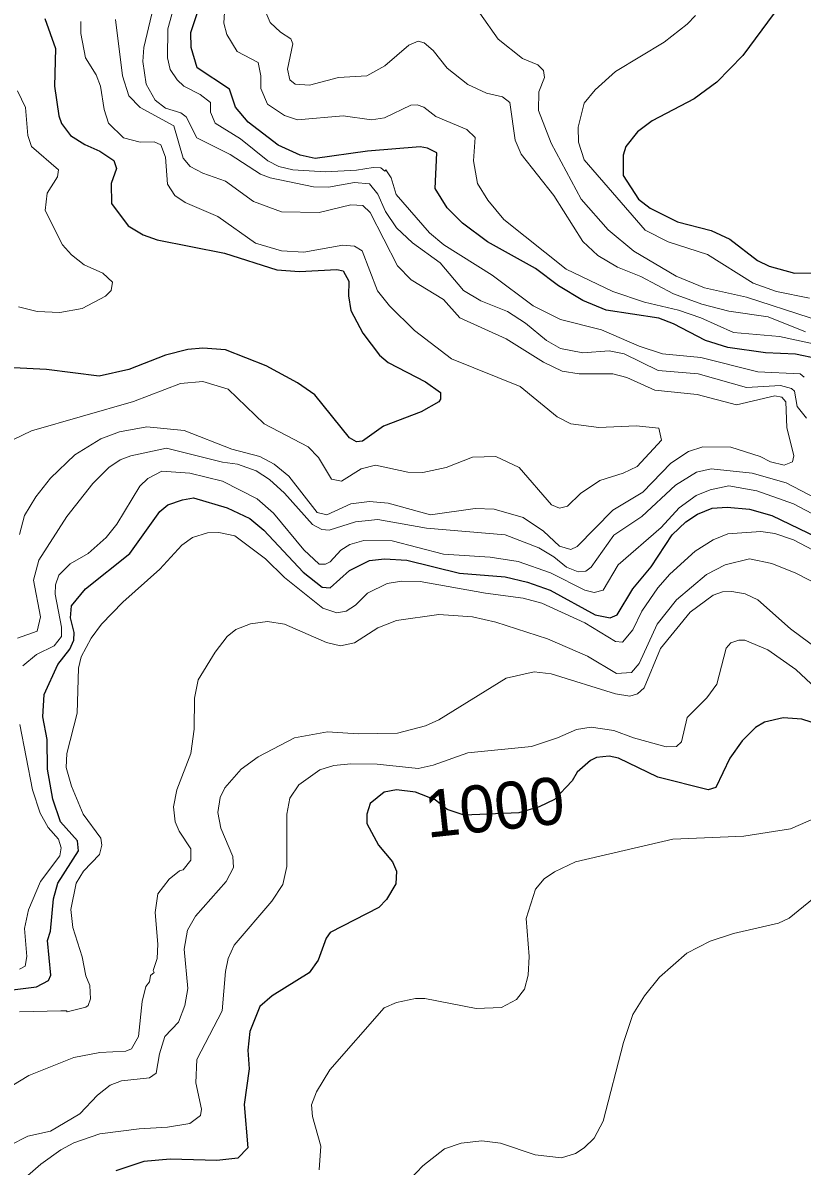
# Model space of a CAD drawing. Extents: x 265 to 291.4, y 7731.5 to 7759.6.
# Drawn here: x 275.919 to 277.244, y 7748.785 to 7750.728 of the extents above; entities that cross this region are included whole.
import ezdxf
from ezdxf.enums import TextEntityAlignment as Align

# ---------------------------------------------------------------- set-up
doc = ezdxf.new("R2010")
doc.units = 0
doc.header["$LTSCALE"] = 0.032
for name, color, linetype, lineweight in [('1', 7, 'Continuous', 25), ('2', 7, 'Continuous', 13), ('61', 7, 'Continuous', 13)]:
    doc.layers.add(name, color=color, linetype=linetype, lineweight=lineweight)

msp = doc.modelspace()

# ---------------------------------------------------------------- linework, layer by layer
at = {"layer": '1'}
for points in [[(277.2702, 7750.1568), (277.2321, 7750.1648), (277.1812, 7750.1671), (277.1175, 7750.1759), (277.0793, 7750.1878), (277.0252, 7750.2165), (276.9998, 7750.226), (276.9107, 7750.2395), (276.8709, 7750.2562), (276.8295, 7750.2809), (276.7906, 7750.3103), (276.7086, 7750.3557), (276.6665, 7750.3875), (276.6402, 7750.4138), (276.6195, 7750.4464), (276.6227, 7750.5068), (276.6068, 7750.5148), (276.5941, 7750.5171), (276.505, 7750.51), (276.4159, 7750.4973), (276.3904, 7750.5028), (276.353, 7750.5203), (276.3021, 7750.5593), (276.2806, 7750.5848), (276.2703, 7750.615), (276.2154, 7750.6516), (276.2051, 7750.6858), (276.2043, 7750.7113), (276.2337, 7750.8004)], [(277.2169, 7750.7733), (277.1429, 7750.6723), (277.0984, 7750.6269), (277.0602, 7750.5991), (276.9886, 7750.5617), (276.964, 7750.5426), (276.9441, 7750.518), (276.9393, 7750.5029), (276.9393, 7750.4686), (276.9655, 7750.4281), (276.9854, 7750.4129), (277.0316, 7750.3899), (277.0889, 7750.3748), (277.1207, 7750.3604), (277.1676, 7750.3238), (277.1875, 7750.3143), (277.2305, 7750.3024), (277.2734, 7750.3032)], [(275.9561, 7750.7351), (275.9744, 7750.6842), (275.9728, 7750.6206), (275.9799, 7750.5697), (275.9847, 7750.557), (275.9998, 7750.5363), (276.0245, 7750.5211), (276.05, 7750.51), (276.0738, 7750.4941), (276.0778, 7750.4806), (276.069, 7750.4551), (276.0698, 7750.4209), (276.0977, 7750.3827), (276.1232, 7750.3676), (276.147, 7750.3589), (276.2616, 7750.3366), (276.3507, 7750.3079), (276.3889, 7750.3056), (276.4525, 7750.3087)], [(276.4525, 7750.3087), (276.4636, 7750.3063), (276.4731, 7750.2889), (276.4724, 7750.2642), (276.4763, 7750.2388), (276.497, 7750.2006), (276.5249, 7750.1632)], [(276.5249, 7750.1632), (276.54, 7750.1504), (276.6036, 7750.1178), (276.6291, 7750.0995), (276.6291, 7750.0884), (276.6259, 7750.0836), (276.5957, 7750.0669), (276.532, 7750.0422), (276.4962, 7750.0168), (276.4859, 7750.016), (276.474, 7750.0224), (276.4151, 7750.0956), (276.3857, 7750.1162), (276.3324, 7750.1449), (276.2632, 7750.1719), (276.225, 7750.1751), (276.1995, 7750.1727), (276.1613, 7750.1632), (276.0993, 7750.1385), (276.0484, 7750.1274), (275.9593, 7750.1385), (275.8352, 7750.1449)], [(275.8781, 7749.0813), (275.9418, 7749.0893), (275.9625, 7749.1004), (275.9664, 7749.1092), (275.9609, 7749.168), (275.9656, 7749.1839), (275.9708, 7749.2388), (275.9781, 7749.2659), (276.0134, 7749.3208), (276.0118, 7749.3375), (275.9831, 7749.3701), (275.9696, 7749.4083), (275.9609, 7749.4592), (275.9601, 7749.5101), (275.9529, 7749.5483), (275.9553, 7749.5865), (275.9784, 7749.6374), (275.999, 7749.6636), (276.0054, 7749.6787), (276.0062, 7749.6915), (275.9998, 7749.7169), (276.0014, 7749.7368), (276.0253, 7749.7662), (276.1009, 7749.8259), (276.1518, 7749.8975), (276.1653, 7749.9086), (276.19, 7749.9174), (276.2091, 7749.9205), (276.2663, 7749.9038), (276.3045, 7749.8855), (276.3284, 7749.8657), (276.3952, 7749.7941), (276.4278, 7749.7686), (276.4413, 7749.7678), (276.474, 7749.7972), (276.5082, 7749.8139), (276.5336, 7749.8171), (276.5718, 7749.8147), (276.6609, 7749.7925), (276.7389, 7749.7861), (276.777, 7749.7774), (276.8152, 7749.7638)], [(277.0228, 7749.8577), (277.0459, 7749.88), (277.0658, 7749.8927), (277.0905, 7749.903), (277.1159, 7749.9046), (277.1541, 7749.9015), (277.1923, 7749.8903), (277.2687, 7749.8537)], [(276.8152, 7749.7638), (276.8916, 7749.7217), (276.9171, 7749.7169), (276.929, 7749.7217), (276.956, 7749.7662), (276.987, 7749.8036), (277.0228, 7749.8577)], [(277.2591, 7749.5395), (277.2432, 7749.5443), (277.2114, 7749.5467), (277.1796, 7749.5395), (277.1644, 7749.53), (277.1414, 7749.5077), (277.1207, 7749.4783), (277.0968, 7749.4281), (277.0841, 7749.4241), (276.9982, 7749.4456), (276.9314, 7749.4782), (276.9155, 7749.4814), (276.894, 7749.479), (276.8836, 7749.4743), (276.8614, 7749.4544), (276.8526, 7749.4393), (276.8226, 7749.4077), (276.7967, 7749.3951), (276.7621, 7749.3851), (276.6692, 7749.3811), (276.64, 7749.3911), (276.62, 7749.407), (276.5861, 7749.4202), (276.5543, 7749.4241), (276.5328, 7749.4202), (276.509, 7749.4011), (276.5034, 7749.3828), (276.5034, 7749.3669), (276.5232, 7749.3303), (276.5471, 7749.3017), (276.5543, 7749.2858), (276.5527, 7749.2643), (276.5368, 7749.238), (276.5241, 7749.2245), (276.4414, 7749.1815), (276.4342, 7749.172), (276.4206, 7749.1346), (276.4055, 7749.1131), (276.3427, 7749.0741), (276.322, 7749.0558), (276.3045, 7749.0137), (276.3013, 7748.9819), (276.3037, 7748.9501), (276.295, 7748.8896), (276.3013, 7748.8156), (276.2846, 7748.7981), (276.2488, 7748.7941), (276.1693, 7748.7965), (276.1247, 7748.7925), (276.077, 7748.7766)]]:
    msp.add_lwpolyline(points, dxfattribs=at)
at = {"layer": '2'}
for points in [[(276.3459, 7750.8982), (276.3435, 7750.8672), (276.3276, 7750.8099), (276.3268, 7750.7574), (276.3395, 7750.7288), (276.357, 7750.7121), (276.3745, 7750.7009)], [(276.1828, 7750.7813), (276.1653, 7750.7176), (276.1645, 7750.6683), (276.1693, 7750.6484), (276.1812, 7750.6309), (276.1924, 7750.6206), (276.2202, 7750.6063), (276.2377, 7750.5927), (276.2377, 7750.576), (276.2456, 7750.5577), (276.2886, 7750.5307), (276.3355, 7750.4933), (276.3538, 7750.4838), (276.3777, 7750.4782), (276.4334, 7750.475), (276.4859, 7750.4774), (276.5145, 7750.4822), (276.5273, 7750.4814), (276.5344, 7750.4758), (276.536, 7750.4782), (276.5447, 7750.4647), (276.5535, 7750.436), (276.61, 7750.3708), (276.6347, 7750.3509), (276.7166, 7750.2992), (276.7866, 7750.2467), (276.8327, 7750.2236), (276.9027, 7750.2061), (276.9664, 7750.1783), (277.0061, 7750.1656), (277.0714, 7750.1592), (277.1684, 7750.1345), (277.24, 7750.1314), (277.2472, 7750.1258)], [(276.6004, 7750.5848), (276.5893, 7750.5888), (276.5782, 7750.588), (276.5336, 7750.5665), (276.5114, 7750.5633), (276.4636, 7750.5697), (276.3857, 7750.5633), (276.3634, 7750.5705), (276.3347, 7750.5896), (276.3236, 7750.6166), (276.3236, 7750.6381), (276.3188, 7750.6604), (276.283, 7750.6794), (276.2655, 7750.7081), (276.2608, 7750.7272), (276.2632, 7750.7749)], [(277.4349, 7750.1043), (277.411, 7750.117), (277.3649, 7750.1528), (277.3546, 7750.1672), (277.353, 7750.2029), (277.3442, 7750.2149), (277.3227, 7750.2204), (277.2575, 7750.2268), (277.1493, 7750.2618), (277.0777, 7750.2777), (277.0292, 7750.2976), (276.9576, 7750.3398), (276.9139, 7750.3764), (276.8677, 7750.4281), (276.8168, 7750.5235), (276.7953, 7750.5792), (276.7961, 7750.611), (276.8057, 7750.6349), (276.8041, 7750.6468), (276.7945, 7750.6564), (276.7683, 7750.6675), (276.7269, 7750.7001), (276.6959, 7750.7447)], [(276.9632, 7749.9738), (277.0045, 7750.0184), (276.9998, 7750.0391), (276.9616, 7750.0431), (276.898, 7750.0399), (276.8502, 7750.0462), (276.8272, 7750.0582), (276.7643, 7750.1099), (276.6474, 7750.1568), (276.5845, 7750.2053), (276.5424, 7750.2467), (276.5217, 7750.2722), (276.4954, 7750.3406), (276.4825, 7750.3486), (276.4626, 7750.3499), (276.3968, 7750.3382), (276.3586, 7750.3406), (276.3141, 7750.3533), (276.2504, 7750.3986), (276.1948, 7750.4225), (276.1773, 7750.4344), (276.1645, 7750.4535), (276.1613, 7750.4997), (276.1534, 7750.5204), (276.1423, 7750.5259), (276.1184, 7750.5251), (276.0897, 7750.5323), (276.0643, 7750.5577), (276.0571, 7750.5808), (276.0508, 7750.6206), (276.0436, 7750.6397), (276.0253, 7750.6683), (276.0173, 7750.7097), (276.0173, 7750.7304)], [(276.0762, 7750.7336), (276.0881, 7750.6381), (276.0993, 7750.6039), (276.1184, 7750.584), (276.1757, 7750.553), (276.1916, 7750.4981), (276.2035, 7750.4838), (276.225, 7750.4726), (276.2632, 7750.4591), (276.3109, 7750.4241), (276.3586, 7750.4066), (276.4223, 7750.4058), (276.4764, 7750.4185), (276.497, 7750.4177), (276.509, 7750.4058), (276.5559, 7750.3151), (276.5789, 7750.2913), (276.6339, 7750.2578), (276.6617, 7750.2268), (276.7405, 7750.191)], [(277.2511, 7750.0558), (277.2352, 7750.0757), (277.2305, 7750.1019), (277.2257, 7750.1067), (277.2066, 7750.1115), (277.1493, 7750.1083), (277.0666, 7750.1314), (276.999, 7750.1369), (276.9409, 7750.1656), (276.9155, 7750.1703), (276.8709, 7750.1671), (276.8327, 7750.1743), (276.8088, 7750.1878), (276.7731, 7750.2173), (276.7428, 7750.2372), (276.6975, 7750.2555), (276.6681, 7750.273), (276.6283, 7750.3199), (276.5814, 7750.3541), (276.5543, 7750.3796), (276.5352, 7750.4074), (276.5225, 7750.4368), (276.5082, 7750.4543), (276.4827, 7750.4567), (276.4382, 7750.4488), (276.4127, 7750.4495), (276.3395, 7750.4647), (276.3228, 7750.471), (276.2711, 7750.5044), (276.2146, 7750.5323), (276.1963, 7750.5681), (276.1876, 7750.5752), (276.1613, 7750.5832), (276.1438, 7750.5967), (276.1287, 7750.6238), (276.1231, 7750.662), (276.1247, 7750.6858), (276.1383, 7750.7431)], [(277.0626, 7750.7407), (277.0483, 7750.7256), (277.0093, 7750.6954), (276.9266, 7750.6452), (276.8916, 7750.6142), (276.8733, 7750.5912), (276.863, 7750.5506), (276.8637, 7750.5251), (276.8733, 7750.4949), (276.9767, 7750.3756), (277.0157, 7750.3557), (277.0825, 7750.3342), (277.1605, 7750.2857), (277.2002, 7750.2714), (277.2559, 7750.2602)], [(276.3745, 7750.7009), (276.3777, 7750.6922), (276.3689, 7750.6492), (276.3729, 7750.6309), (276.3817, 7750.6238), (276.4063, 7750.6222), (276.4557, 7750.6349), (276.5034, 7750.6381), (276.5344, 7750.6548), (276.575, 7750.6898), (276.5909, 7750.6969), (276.6012, 7750.6938), (276.6163, 7750.681), (276.6402, 7750.6508), (276.6752, 7750.623), (276.707, 7750.6086), (276.7341, 7750.6023), (276.7468, 7750.5927), (276.7556, 7750.5283), (276.7659, 7750.5045), (276.8216, 7750.4344), (276.8709, 7750.3565), (276.8964, 7750.3326), (276.9298, 7750.3127), (276.9696, 7750.2968), (277.0252, 7750.2674), (277.073, 7750.2499), (277.1191, 7750.238), (277.1859, 7750.2284), (277.2496, 7750.2029)], [(275.9116, 7750.2451), (275.9434, 7750.2372), (275.9816, 7750.2356), (276.0197, 7750.2427), (276.0595, 7750.2634), (276.0691, 7750.273), (276.0714, 7750.2873), (276.0547, 7750.3024), (276.0229, 7750.3167), (276.0014, 7750.3334), (275.9863, 7750.3509), (275.9569, 7750.409), (275.9601, 7750.4384), (275.9776, 7750.4663), (275.9792, 7750.4782), (275.9338, 7750.518), (275.9275, 7750.5363), (275.9235, 7750.584), (275.91, 7750.6126)], [(276.7094, 7750.4265), (276.6919, 7750.4551), (276.6848, 7750.4933), (276.6879, 7750.5331), (276.6736, 7750.5466), (276.6211, 7750.5689), (276.6004, 7750.5848)], [(277.2917, 7750.1759), (277.205, 7750.195), (277.1271, 7750.2014), (277.0714, 7750.2268), (277.0332, 7750.2395), (276.9759, 7750.2531), (276.9218, 7750.2714), (276.8423, 7750.3095), (276.7365, 7750.3939), (276.7094, 7750.4265)], [(276.7405, 7750.191), (276.8041, 7750.1512), (276.8359, 7750.1361), (276.8646, 7750.1314), (276.9218, 7750.1314), (276.9457, 7750.125), (276.9934, 7750.1035)], [(275.9028, 7750.02), (275.9338, 7750.0343), (276.1072, 7750.0844), (276.1868, 7750.1147), (276.225, 7750.1186), (276.2679, 7750.1051), (276.3292, 7750.0462), (276.404, 7750.0073), (276.4215, 7749.989), (276.4437, 7749.9524), (276.4604, 7749.9492), (276.4938, 7749.9699), (276.5185, 7749.9762), (276.5734, 7749.9643), (276.5989, 7749.9635), (276.6386, 7749.9723), (276.6832, 7749.9898), (276.723, 7749.9906), (276.7627, 7749.9723), (276.8176, 7749.9086)], [(276.9934, 7750.1035), (277.065, 7750.0964), (277.1318, 7750.0789), (277.1971, 7750.094), (277.209, 7750.0916), (277.2161, 7750.0836), (277.2177, 7750.0399), (277.2297, 7749.9922), (277.2273, 7749.9818), (277.213, 7749.9762), (277.1899, 7749.9818), (277.1724, 7749.9906), (277.1223, 7750.0065), (277.0746, 7750.0073), (277.0507, 7749.9993), (277.0205, 7749.9794), (276.9727, 7749.9301), (276.9218, 7749.8999), (276.8614, 7749.8378), (276.8502, 7749.833), (276.8311, 7749.8386), (276.8041, 7749.8641), (276.7691, 7749.8871), (276.7198, 7749.9015), (276.688, 7749.9023), (276.6116, 7749.8919), (276.54, 7749.9118), (276.5082, 7749.9142), (276.4764, 7749.9102), (276.4358, 7749.8919), (276.4191, 7749.8959), (276.3713, 7749.9572), (276.3459, 7749.9778), (276.322, 7749.9906), (276.2743, 7750.0033), (276.1932, 7750.0351), (276.1295, 7750.0415), (276.0834, 7750.0327), (276.0516, 7750.0208), (276.007, 7749.9937), (275.9657, 7749.954), (275.941, 7749.9222), (275.9219, 7749.8903), (275.9131, 7749.8585)], [(275.91, 7749.6819), (275.9434, 7749.6938), (275.9489, 7749.7185), (275.937, 7749.7806), (275.9458, 7749.8148), (275.9935, 7749.8887), (276.038, 7749.9452), (276.0651, 7749.9723), (276.0842, 7749.985), (276.1025, 7749.9922), (276.1629, 7750.0049), (276.2584, 7749.981), (276.2838, 7749.9778), (276.3157, 7749.9667), (276.3379, 7749.9516), (276.3634, 7749.9285), (276.4111, 7749.8752), (276.427, 7749.8665), (276.4398, 7749.8657), (276.4843, 7749.88), (276.5225, 7749.884), (276.6052, 7749.8688), (276.7389, 7749.8577), (276.7961, 7749.8354), (276.8216, 7749.8203), (276.8431, 7749.8028), (276.863, 7749.7949), (276.8757, 7749.7957), (276.8852, 7749.8028), (276.9234, 7749.8569), (276.9711, 7749.8887), (277.0284, 7749.942), (277.0642, 7749.9643), (277.0889, 7749.9699), (277.1589, 7749.9627), (277.2162, 7749.946), (277.3052, 7749.8999)], [(276.8176, 7749.9086), (276.8311, 7749.903), (276.8446, 7749.9062), (276.8669, 7749.9277), (276.8996, 7749.95), (276.9393, 7749.9627), (276.9632, 7749.9738)], [(276.2027, 7749.9627), (276.155, 7749.9659), (276.1311, 7749.9532), (276.1176, 7749.9404), (276.0786, 7749.876), (276.0603, 7749.8529), (276.0301, 7749.8259)], [(277.314, 7749.8657), (277.2289, 7749.9102), (277.1668, 7749.9325), (277.1191, 7749.9412), (277.0873, 7749.9341), (277.0634, 7749.9245), (277.0348, 7749.9038), (277.0037, 7749.8704), (276.9306, 7749.8068), (276.9051, 7749.7638), (276.89, 7749.7599), (276.8741, 7749.7638), (276.816, 7749.7933), (276.7611, 7749.8124), (276.7134, 7749.8195), (276.6339, 7749.8251), (276.5464, 7749.8474), (276.4986, 7749.8482), (276.4748, 7749.841), (276.4596, 7749.8315), (276.4413, 7749.8116), (276.4334, 7749.8076), (276.4223, 7749.8076), (276.3968, 7749.8323), (276.3451, 7749.8943), (276.3172, 7749.919), (276.2584, 7749.9492), (276.2027, 7749.9627)], [(276.0094, 7749.2659), (276.022, 7749.2858), (276.0492, 7749.3144), (276.0531, 7749.3303), (276.0515, 7749.3422), (276.0213, 7749.3828), (276.0014, 7749.4305), (275.9927, 7749.4624), (275.9935, 7749.4862), (276.011, 7749.5546), (276.0134, 7749.631), (276.0181, 7749.6501), (276.0348, 7749.6819), (276.0523, 7749.7058), (276.0889, 7749.7432), (276.1518, 7749.7996), (276.1892, 7749.8402), (276.2075, 7749.8529), (276.2329, 7749.8609), (276.252, 7749.8617), (276.2791, 7749.8561), (276.3316, 7749.8171), (276.3634, 7749.7853), (276.4286, 7749.7328), (276.4525, 7749.7249), (276.4684, 7749.728), (276.4843, 7749.7384), (276.505, 7749.7583), (276.5384, 7749.775), (276.5623, 7749.779), (276.5941, 7749.7782), (276.7055, 7749.7583), (276.7691, 7749.7503), (276.8009, 7749.7416), (276.8741, 7749.7082), (276.9266, 7749.6763), (276.9385, 7749.6755), (276.956, 7749.6962), (276.9711, 7749.7281), (276.9982, 7749.7678), (277.0189, 7749.7909), (277.0618, 7749.8299), (277.0921, 7749.849), (277.1175, 7749.8593), (277.1732, 7749.8633), (277.1971, 7749.8601), (277.2289, 7749.849), (277.2949, 7749.8148)], [(276.0301, 7749.8259), (275.9991, 7749.8084), (275.98, 7749.7893), (275.9744, 7749.7726), (275.9736, 7749.7567), (275.9847, 7749.701), (275.9847, 7749.6851), (275.972, 7749.6692), (275.9418, 7749.6541), (275.9187, 7749.635)], [(277.2758, 7749.7702), (277.2329, 7749.7925), (277.1923, 7749.8092), (277.1541, 7749.8171), (277.1127, 7749.8068), (277.0809, 7749.7901), (277.03, 7749.7471), (276.9974, 7749.7058), (276.9664, 7749.639), (276.9536, 7749.6238), (276.9282, 7749.6222), (276.8789, 7749.6517), (276.8105, 7749.6811), (276.723, 7749.709), (276.6832, 7749.7185)], [(275.8964, 7748.8196), (275.9275, 7748.8355), (275.9657, 7748.8443), (276.0158, 7748.8737), (276.046, 7748.9055), (276.0675, 7748.9222), (276.0866, 7748.9294), (276.1343, 7748.9349), (276.1454, 7748.9429), (276.151, 7748.9755), (276.1605, 7749.005), (276.1836, 7749.0296), (276.1945, 7749.0575), (276.1992, 7749.0866), (276.1932, 7749.1537), (276.1987, 7749.1855), (276.2122, 7749.2094), (276.2647, 7749.2683), (276.2767, 7749.2921), (276.2759, 7749.3112), (276.2552, 7749.359), (276.2504, 7749.386), (276.2544, 7749.4115), (276.2624, 7749.4274), (276.2902, 7749.4592), (276.3188, 7749.4806), (276.3809, 7749.5125), (276.4366, 7749.5228), (276.4891, 7749.5196), (276.5559, 7749.5204), (276.6036, 7749.5332), (276.6259, 7749.5435), (276.7405, 7749.6143), (276.7882, 7749.6246), (276.8168, 7749.6215), (276.9266, 7749.5872), (276.9505, 7749.5833), (276.964, 7749.5872), (276.9751, 7749.5976), (277.0029, 7749.6644), (277.0531, 7749.7265), (277.0921, 7749.7551), (277.108, 7749.7607), (277.1239, 7749.7615), (277.1469, 7749.7575), (277.1684, 7749.7471), (277.2241, 7749.6978), (277.2718, 7749.662)], [(276.6832, 7749.7185), (276.6259, 7749.7225), (276.5543, 7749.7121), (276.5225, 7749.6994), (276.4827, 7749.6739), (276.4589, 7749.6692), (276.435, 7749.6747)], [(276.435, 7749.6747), (276.3634, 7749.7058), (276.3348, 7749.7105), (276.3061, 7749.7066), (276.2807, 7749.697), (276.2663, 7749.6851), (276.2457, 7749.6581), (276.217, 7749.6111), (276.2107, 7749.5801), (276.2099, 7749.5276), (276.2043, 7749.4862), (276.1804, 7749.4242), (276.1749, 7749.3955), (276.178, 7749.3701), (276.1844, 7749.3542), (276.2043, 7749.324), (276.2043, 7749.3049), (276.1916, 7749.2881), (276.1852, 7749.2865), (276.1677, 7749.2722), (276.1486, 7749.2476), (276.1438, 7749.2158), (276.1486, 7749.1617), (276.147, 7749.1378), (276.1406, 7749.1171), (276.1422, 7749.1139), (276.1359, 7749.1084), (276.1343, 7749.098), (276.1279, 7749.0901), (276.1215, 7749.0646), (276.1152, 7749.0049), (276.1033, 7748.9843), (276.0937, 7748.9803), (276.05, 7748.9779), (276.0054, 7748.9692), (275.9291, 7748.9389), (275.9004, 7748.9214)], [(277.3021, 7749.5642), (277.2329, 7749.6286), (277.1851, 7749.662), (277.1462, 7749.6787), (277.1358, 7749.6787), (277.1223, 7749.6739), (277.1143, 7749.6652), (277.0984, 7749.604), (277.0817, 7749.5809), (277.0483, 7749.5475), (277.0387, 7749.5061), (277.03, 7749.4981), (277.0125, 7749.4973), (276.9568, 7749.5125), (276.9234, 7749.5252), (276.8852, 7749.5308), (276.8598, 7749.5268), (276.828, 7749.5125), (276.7834, 7749.4981), (276.6752, 7749.487), (276.6164, 7749.4663), (276.5909, 7749.4608), (276.5209, 7749.4679), (276.4764, 7749.4687), (276.4477, 7749.4655), (276.4239, 7749.4584), (276.3881, 7749.4329), (276.3729, 7749.4099), (276.3674, 7749.3828), (276.3674, 7749.2937), (276.361, 7749.2635), (276.3419, 7749.2349), (276.2783, 7749.1601), (276.2679, 7749.1378), (276.2632, 7749.1155), (276.2576, 7749.0487), (276.2146, 7748.966), (276.213, 7748.9262), (276.2226, 7748.8817), (276.221, 7748.8705), (276.2027, 7748.857), (276.1645, 7748.8506), (276.1168, 7748.8482), (276.05, 7748.8395), (276.0054, 7748.8244), (275.9832, 7748.8124), (275.9497, 7748.7878), (275.8416, 7748.6947)], [(275.9139, 7749.5356), (275.9354, 7749.4242), (275.9481, 7749.3844), (275.9617, 7749.3605), (275.9792, 7749.3406), (275.9839, 7749.3255), (275.9815, 7749.312), (275.9489, 7749.2683), (275.9283, 7749.2205), (275.9219, 7749.1887), (275.9259, 7749.141), (275.9227, 7749.1243), (275.9131, 7749.1195)], [(276.4223, 7748.7782), (276.4254, 7748.8188), (276.4111, 7748.8689), (276.4095, 7748.8888), (276.4183, 7748.9111), (276.4405, 7748.9485), (276.5328, 7749.0535), (276.5543, 7749.063), (276.5861, 7749.0694), (276.602, 7749.0694), (276.6895, 7749.0527), (276.7325, 7749.0543), (276.758, 7749.0678), (276.7715, 7749.0853), (276.7778, 7749.1092), (276.7794, 7749.141), (276.7746, 7749.2054), (276.7906, 7749.2555), (276.8049, 7749.273), (276.8224, 7749.285), (276.8582, 7749.3017), (277.0236, 7749.3406), (277.1446, 7749.3454), (277.2241, 7749.3581), (277.31, 7749.3955)], [(275.9132, 7749.0471), (275.9832, 7749.0487), (275.9882, 7749.0486), (275.9929, 7749.0486), (275.9943, 7749.0471), (276.0261, 7749.0551), (276.03, 7749.0578), (276.0339, 7749.0691), (276.0325, 7749.0917), (276.026, 7749.1082), (276.0197, 7749.1402), (276.0038, 7749.1903), (276.0002, 7749.2208), (276.0094, 7749.2659)], [(277.2702, 7749.246), (277.2217, 7749.2062), (277.2034, 7749.1975), (277.1271, 7749.18), (277.0873, 7749.1672), (277.0475, 7749.1465), (277.0014, 7749.106), (276.9759, 7749.0742), (276.956, 7749.0424), (276.9401, 7748.9946), (276.9051, 7748.861), (276.89, 7748.8323), (276.8733, 7748.8156), (276.8582, 7748.8061), (276.8343, 7748.7989), (276.7898, 7748.8037), (276.7309, 7748.8236), (276.6991, 7748.8276), (276.6641, 7748.8236), (276.6355, 7748.814), (276.5988, 7748.7854), (276.5774, 7748.7623)]]:
    msp.add_lwpolyline(points, dxfattribs=at)

# ---------------------------------------------------------------- texts
at = {"layer": '61'}
msp.add_text('1000', height=0.08, rotation=6.096, dxfattribs=at).set_placement((276.7247, 7749.3553), align=Align.CENTER)

doc.saveas('drawing.dxf')
